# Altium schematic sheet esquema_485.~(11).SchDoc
size A4
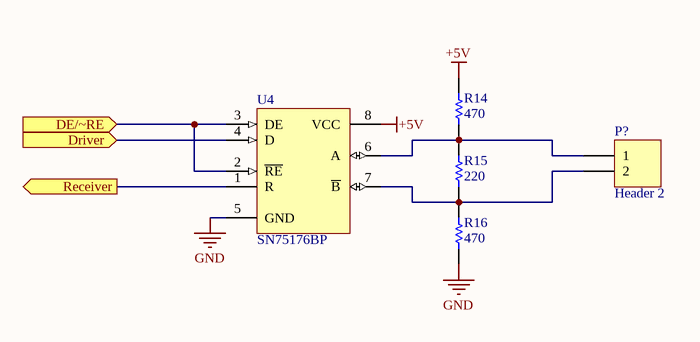
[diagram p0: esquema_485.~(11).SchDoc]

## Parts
P?  Header 2  [HDR1X2]
R14  value 470  [1005[0402]]  (hidden comment: Carbon 1/8w 5%)
R15  value 220  [1005[0402]]  (hidden comment: Carbon 1/8w 5%)
R16  value 470  [1005[0402]]  (hidden comment: Carbon 1/8w 5%)
U4  SN75176BP  [P008]

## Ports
DE/~RE (in), Driver (in), Receiver (out)

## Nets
+5V: R14.2 U4.8(VCC)
GND: R16.1 U4.5(GND)
DE/~RE: U4.2(~{RE}) U4.3(DE) ; port DE/~RE
Driver: U4.4(D) ; port Driver
Receiver: U4.1(R) ; port Receiver
NetP?_1: P?.1 R14.1 R15.2 U4.6(A)
NetP?_2: P?.2 R15.1 R16.2 U4.7(~{B})

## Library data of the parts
P? = Header 2: Header, 2-Pin
R14-R16 = Res Semi: Semiconductor Resistor
U4 = SN75176BP: Differential Bus Transceiver; Note: Receiver Hysteresis of 50mV Typical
